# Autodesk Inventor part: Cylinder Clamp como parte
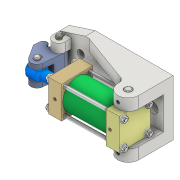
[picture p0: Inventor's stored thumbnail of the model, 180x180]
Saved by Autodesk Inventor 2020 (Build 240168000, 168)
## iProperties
Created: 2020-02
Part Number: Cylinder Clamp como parte
Material: Generic
Document SubType Name: Modeling
Designer: user
Density: 1 g/cm^3
Appearance: Default
Author: user
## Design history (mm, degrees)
derived "Cylinder Clamp.iam"
body "Solid1"
node "Cylinder Base.ipt:1"
node "Clamp.ipt:1"
body "Solid2"
node "Long Shaft.ipt:1"
body "Solid3"
node "Short Shaft.ipt:1"
body "Solid4"
node "Lock Pin.ipt:1"
body "Solid5"
node "Lock Pin.ipt:2"
body "Solid6"
node "6mm SHCS.ipt:1"
body "Solid7"
node "6mm SHCS.ipt:2"
body "Solid8"
node "Cylinder Body Sub_Assy.iam:1::Cylinder Head Cover_Front.ipt:"
body "Solid9"
node "Cylinder Body Sub_Assy.iam:1::Cylinder Body.ipt:1"
body "Solid10"
node "Cylinder Body Sub_Assy.iam:1::Cylinder Head Cover_Back.ipt:1"
body "Solid11"
node "Cylinder Body Sub_Assy.iam:1::M5 Threaded Rod.ipt:1"
body "Solid12"
node "Cylinder Body Sub_Assy.iam:1::Metric Hex Flange Nuts - Metri"
body "Solid13"
node "Cylinder Body Sub_Assy.iam:1::Metric Hex Flange Nuts - Metri"
body "Solid14"
node "Cylinder Body Sub_Assy.iam:1::M5 Threaded Rod.ipt:2"
body "Solid15"
node "Cylinder Body Sub_Assy.iam:1::Metric Hex Flange Nuts - Metri"
body "Solid16"
node "Cylinder Body Sub_Assy.iam:1::Metric Hex Flange Nuts - Metri"
body "Solid17"
node "Cylinder Body Sub_Assy.iam:1::M5 Threaded Rod.ipt:3"
body "Solid18"
node "Cylinder Body Sub_Assy.iam:1::Metric Hex Flange Nuts - Metri"
body "Solid19"
node "Cylinder Body Sub_Assy.iam:1::Metric Hex Flange Nuts - Metri"
body "Solid20"
node "Cylinder Body Sub_Assy.iam:1::M5 Threaded Rod.ipt:4"
body "Solid21"
node "Cylinder Body Sub_Assy.iam:1::Metric Hex Flange Nuts - Metri"
body "Solid22"
node "Cylinder Body Sub_Assy.iam:1::Metric Hex Flange Nuts - Metri"
body "Solid23"
node "Cylinder Body Sub_Assy.iam:1::Piston Rod.ipt:1"
body "Solid24"
node "Cylinder Body Sub_Assy.iam:1::Piston.ipt:1"
body "Solid25"
node "Cylinder Body Sub_Assy.iam:1::AS 1969 (External Tooth Lock W"
body "Solid26"
node "Cylinder Body Sub_Assy.iam:1::ANSI B18.2.4.2M M8x1.25:1"
body "Solid27"
node "ANSI B 27.7M 3AMI-7:1"
body "Solid28"
node "ANSI B 27.7M 3AMI-7:2"
body "Solid29"
node "ANSI B 27.7M 3AMI-7:3"
body "Solid30"
node "ANSI B 27.7M 3AMI-7:4"
body "Solid31"
other parameters: "LENGTH" = 25.4 [user parameter], "LENGTH_1" = 25.4 [user parameter], "LENGTH_2" = 25.4 [user parameter], "LENGTH_3" = 25.4 [user parameter], "d32" = 6 [user parameter], "LENGTH_4" = 25.4 [user parameter]
